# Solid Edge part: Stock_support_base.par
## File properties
Title: Stock Support Base
Author: Abhinav Rai
Template: Normal.par
Last saved by: CADCIM
Revision: 18
Application: Solid Edge
Material: aluminum
Accuracy: 0.99
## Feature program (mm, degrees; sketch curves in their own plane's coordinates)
sketch for "unnamed RevolvedProtrusion 1" plane through (0, 0, 0) normal (0, -1, 0) x-axis (1, 0, 0)
  line (0, 29.2468) -> (71.7103, 29.2468)
  line (71.7103, 29.2468) -> (71.7103, 19.7218)
  line (71.7103, 19.7218) -> (165.1, -256.5032)
  line (165.1, -256.5032) -> (215.9, -256.5032)
  line (215.9, -256.5032) -> (215.9, -281.9032)
  line (215.9, -281.9032) -> (156.9298, -281.9032)
  line (156.9298, -281.9032) -> (85.052, -69.3053)
  arc centre (73.021, -73.3729) radius 12.7 from (60.325, -73.0538) to (85.052, -69.3053) cw
  line (60.325, -73.0538) -> (57.15, -199.3532)
  line (57.15, -199.3532) -> (0, -199.3532)
  line (0, 29.2468) -> (0, -199.3532)
revolve "unnamed RevolvedProtrusion 1" add full turn 360 deg
sketch for "unnamed Hole 1" plane through (0, 0, 29.2468) normal (0, 0, 1) x-axis (1, 0, 0)
  hole centre (0, 0) bore radius 38.1
hole "unnamed Hole 1" through
sketch for "ExtrudedProtrusion_2" plane through (0, 0, -256.5032) normal (0, 0, 1) x-axis (0, 1, 0)
  arc centre (0, -119.2664) radius 41.0756 from (-18.7686, -155.8034) to (18.7686, -155.8034) ccw
  line (-18.7686, -197.1314) -> (-18.7686, -155.8034)
  arc centre (0, -197.1314) radius 18.7686 from (18.7686, -197.1314) to (-18.7686, -197.1314) cw
  line (18.7686, -197.1314) -> (18.7686, -155.8034)
extrude "ExtrudedProtrusion_2" add finite 12.7 along +normal
sketch for "unnamed Hole 2" plane through (187.8036, 0, -243.8032) normal (0, 0, 1) x-axis (1, 0, 0)
hole "unnamed Hole 2" through
fillet "Round_4" radius 3.175
pattern "unnamed Pattern 1" of "ExtrudedProtrusion_2", "unnamed Hole 2", "Round_4"
pattern "unnamed Pattern 2"
sketch for "ExtrudedProtrusion_3" plane through (0, -134.62, 0) normal (0, -1, 0) x-axis (1, 0, 0)
  circle centre (0, -2.5032) radius 19.05
extrude "ExtrudedProtrusion_3" add  Plane_Distance = 134.62 mm
adv blend "unnamed AdvBlend 1"
sketch for "ExtrudedProtrusion_4" plane through (0, -134.62, -2.5032) normal (0, -1, 0) x-axis (1, 0, 0)
  circle centre (0, -3.81) radius 22.225
extrude "ExtrudedProtrusion_4" add finite 9.525 along +normal
mirror "unnamed Mirror 1" of "ExtrudedProtrusion_4", "unnamed AdvBlend 1", "ExtrudedProtrusion_3" about plane through (0, 0, 0) normal (0, -1, 0)
extrude "unnamed Protrusion 1" add
adv blend "unnamed AdvBlend 2"
extrude "unnamed Protrusion 2" add finite 9.525
sketch for "ExtrudedProtrusion_7" plane through (104.775, 0, 0) normal (1, 0, 0) x-axis (0, 1, 0)
  circle centre (0, -167.6032) radius 19.05
extrude "ExtrudedProtrusion_7" add finite 41.275 along +normal  Plane_Distance = 104.775 mm
sketch for "unnamed Hole 3" plane through (146.05, 0, -167.6032) normal (1, 0, 0) x-axis (0, 1, 0)
  hole centre (0, 0) bore radius 7.9375
hole "unnamed Hole 3" through
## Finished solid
Body 1: solid body, 54 faces, 95 edges, 41 vertices.
  Faces by surface: plane 26, cylinder 19, torus 4, cone 3, blend 2
  Edges by curve: circle 57, intersection 20, line 18
Bounding box of the edges (mm; curved faces can reach further): 431.800 x 431.800 x 311.150, from (-215.9, -215.9, -281.9032) to (215.9, 215.9, 29.2468).
Cylindrical faces by radius (mm): R7.9375 x1, R11.1125 x3, R15.875 x3, R18.7686 x3, R19.05 x4, R22.225 x2, R38.1 x1, R71.7103 x1, R215.9 x1
Conical faces (half-angle, radius in mm at the cone's reference point): 1.44 deg R60.325 x1, 18.68 deg R71.7103 x1, 18.68 deg R156.9298 x1
Toroidal faces (ring radius, tube radius in mm): R73.021 r12.7 x1, R163.0843 r3.175 x3
Planar faces by outward normal: +x 1, +y 4, +z 10, -x 1, -y 4, -z 2, oblique 4
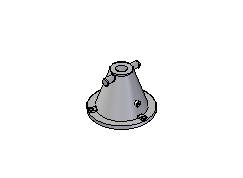
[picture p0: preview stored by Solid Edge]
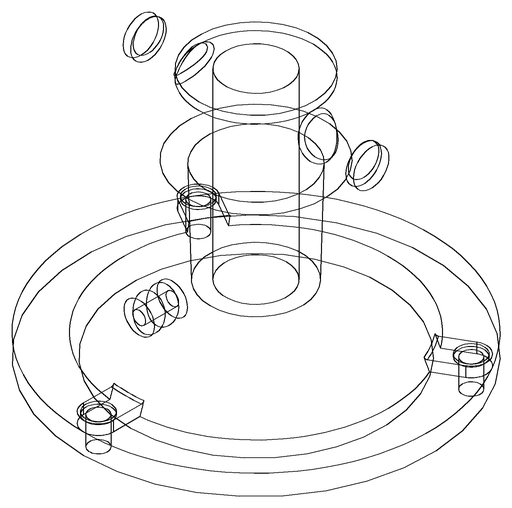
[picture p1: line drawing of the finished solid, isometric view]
